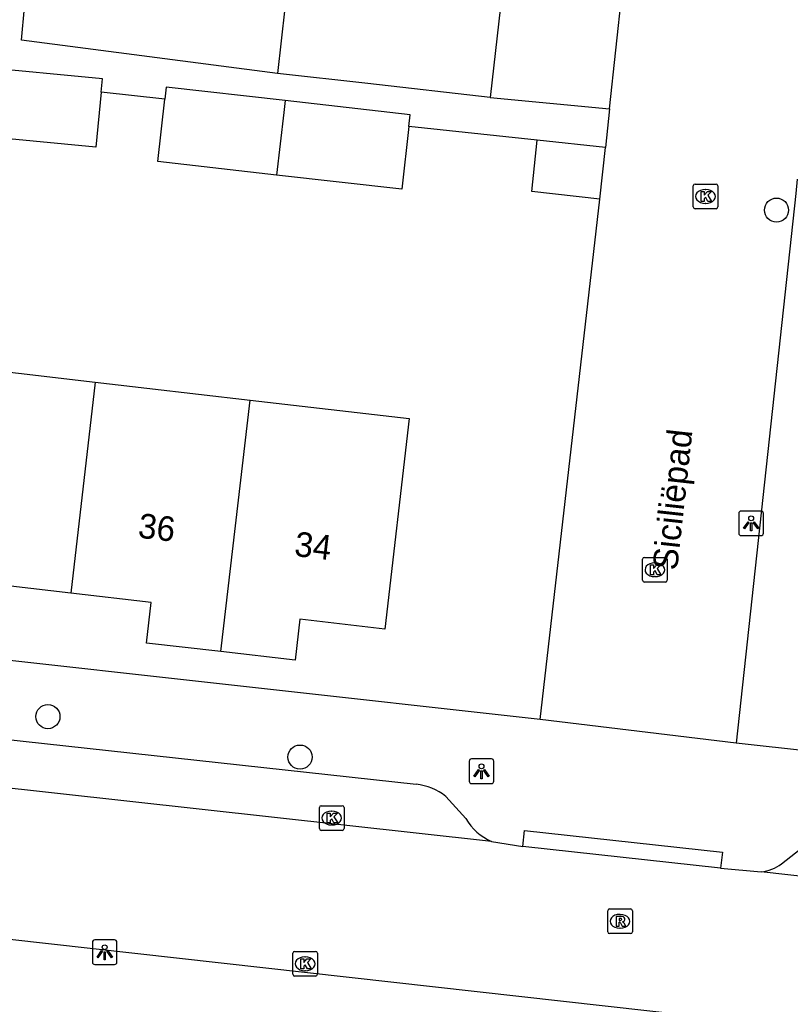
# Model space of a CAD drawing. Extents: x 162082 to 163393, y 388091 to 388632.
# Drawn here: x 162765.6 to 162796.87, y 388467.11 to 388507.04 of the extents above; entities that cross this region are included whole.
import ezdxf

# ---------------------------------------------------------------- set-up
doc = ezdxf.new("R2010")
doc.units = 0
for name, color, linetype in [('IMGEO_Boom', 7, 'Continuous'), ('IMGEO_Kolk', 7, 'Continuous'), ('IMGEO_Lichtpunt', 7, 'Continuous'), ('IMGEO_Openbare_ruimte_label', 7, 'Continuous'), ('IMGEO_Pand', 7, 'Continuous'), ('IMGEO_Pand_nummerreeks', 7, 'Continuous'), ('IMGEO_Rijbaan_lokaal_open', 7, 'Continuous'), ('IMGEO_Rioolput', 7, 'Continuous'), ('IMGEO_Voetpad_open', 7, 'Continuous')]:
    doc.layers.add(name, color=color, linetype=linetype)

msp = doc.modelspace()

# ---------------------------------------------------------------- linework, layer by layer
at = {"layer": 'IMGEO_Boom'}
for centre in [(162796.309, 388499.32), (162766.75, 388478.777), (162776.978, 388477.137)]:
    msp.add_circle(centre, 0.489, dxfattribs=at)
at = {"layer": 'IMGEO_Kolk'}
for p, q in [((162793.005, 388500.375), (162793.857, 388500.375)), ((162792.93, 388499.449), (162792.93, 388500.301)), ((162793.418, 388500.155), (162793.443, 388500.155)), ((162793.931, 388500.301), (162793.931, 388499.449)), ((162793.441, 388499.595), (162793.416, 388499.595)), ((162793.857, 388499.375), (162793.005, 388499.375)), ((162790.95, 388485.234), (162791.802, 388485.234)), ((162790.875, 388484.308), (162790.875, 388485.16)), ((162791.363, 388485.014), (162791.388, 388485.014)), ((162791.876, 388485.16), (162791.876, 388484.308)), ((162791.386, 388484.454), (162791.361, 388484.454)), ((162791.802, 388484.234), (162790.95, 388484.234)), ((162777.762, 388474.238), (162777.762, 388475.09)), ((162777.837, 388475.164), (162778.689, 388475.164)), ((162778.25, 388474.944), (162778.275, 388474.944)), ((162778.763, 388475.09), (162778.763, 388474.238)), ((162778.689, 388474.164), (162777.837, 388474.164)), ((162778.273, 388474.384), (162778.248, 388474.384)), ((162776.759, 388469.253), (162777.611, 388469.253)), ((162776.684, 388468.327), (162776.684, 388469.179)), ((162777.172, 388469.033), (162777.197, 388469.033)), ((162777.685, 388469.179), (162777.685, 388468.327)), ((162777.195, 388468.473), (162777.17, 388468.473)), ((162777.611, 388468.253), (162776.759, 388468.253))]:
    msp.add_line(p, q, dxfattribs=at)
for points in [[(162793.005, 388500.375), (162793.857, 388500.375)], [(162792.93, 388499.449), (162792.93, 388500.301)], [(162793.251, 388500.075), (162793.374, 388500.075), (162793.374, 388499.924), (162793.504, 388500.075), (162793.668, 388500.075), (162793.522, 388499.924), (162793.675, 388499.675), (162793.523, 388499.675), (162793.438, 388499.839), (162793.374, 388499.772), (162793.374, 388499.675), (162793.251, 388499.675), (162793.251, 388500.075)], [(162793.931, 388500.301), (162793.931, 388499.449)], [(162793.857, 388499.375), (162793.005, 388499.375)], [(162790.95, 388485.234), (162791.802, 388485.234)], [(162790.875, 388484.308), (162790.875, 388485.16)], [(162791.196, 388484.934), (162791.319, 388484.934), (162791.319, 388484.783), (162791.449, 388484.934), (162791.613, 388484.934), (162791.467, 388484.783), (162791.62, 388484.534), (162791.468, 388484.534), (162791.383, 388484.698), (162791.319, 388484.631), (162791.319, 388484.534), (162791.196, 388484.534), (162791.196, 388484.934)], [(162791.876, 388485.16), (162791.876, 388484.308)], [(162791.802, 388484.234), (162790.95, 388484.234)], [(162777.762, 388474.238), (162777.762, 388475.09)], [(162777.837, 388475.164), (162778.689, 388475.164)], [(162778.083, 388474.864), (162778.206, 388474.864), (162778.206, 388474.713), (162778.336, 388474.864), (162778.5, 388474.864), (162778.354, 388474.713), (162778.507, 388474.464), (162778.355, 388474.464), (162778.27, 388474.628), (162778.206, 388474.561), (162778.206, 388474.464), (162778.083, 388474.464), (162778.083, 388474.864)], [(162778.763, 388475.09), (162778.763, 388474.238)], [(162778.689, 388474.164), (162777.837, 388474.164)], [(162776.759, 388469.253), (162777.611, 388469.253)], [(162776.684, 388468.327), (162776.684, 388469.179)], [(162777.005, 388468.953), (162777.128, 388468.953), (162777.128, 388468.802), (162777.258, 388468.953), (162777.422, 388468.953), (162777.276, 388468.802), (162777.429, 388468.553), (162777.277, 388468.553), (162777.192, 388468.717), (162777.128, 388468.65), (162777.128, 388468.553), (162777.005, 388468.553), (162777.005, 388468.953)], [(162777.685, 388469.179), (162777.685, 388468.327)], [(162777.611, 388468.253), (162776.759, 388468.253)]]:
    msp.add_lwpolyline(points, dxfattribs=at)
for centre, start, end in [((162793.007, 388500.299), 91.552, 178.448), ((162793.007, 388500.299), 91.552, 178.448), ((162793.855, 388500.299), 1.552, 88.448), ((162793.855, 388500.299), 1.552, 88.448), ((162793.007, 388499.451), 181.552, 268.448), ((162793.007, 388499.451), 181.552, 268.448), ((162793.855, 388499.451), 271.552, 358.448), ((162793.855, 388499.451), 271.552, 358.448), ((162790.952, 388485.158), 91.552, 178.448), ((162790.952, 388485.158), 91.552, 178.448), ((162791.8, 388485.158), 1.552, 88.448), ((162791.8, 388485.158), 1.552, 88.448), ((162790.952, 388484.31), 181.552, 268.448), ((162790.952, 388484.31), 181.552, 268.448), ((162791.8, 388484.31), 271.552, 358.448), ((162791.8, 388484.31), 271.552, 358.448), ((162777.839, 388475.088), 91.552, 178.448), ((162777.839, 388475.088), 91.552, 178.448), ((162778.687, 388475.088), 1.552, 88.448), ((162778.687, 388475.088), 1.552, 88.448), ((162777.839, 388474.24), 181.552, 268.448), ((162777.839, 388474.24), 181.552, 268.448), ((162778.687, 388474.24), 271.552, 358.448), ((162778.687, 388474.24), 271.552, 358.448), ((162776.761, 388469.177), 91.552, 178.448), ((162776.761, 388469.177), 91.552, 178.448), ((162777.609, 388469.177), 1.552, 88.448), ((162777.609, 388469.177), 1.552, 88.448), ((162776.761, 388468.329), 181.552, 268.448), ((162776.761, 388468.329), 181.552, 268.448), ((162777.609, 388468.329), 271.552, 358.448), ((162777.609, 388468.329), 271.552, 358.448)]:
    msp.add_arc(centre, 0.0765, start, end, dxfattribs=at)
for centre, major_axis, ratio, start_param, end_param in [((162793.417, 388499.875), (-0.387, 0.002), 0.722429, 4.712389, 7.853982), ((162793.442, 388499.875), (-0.39, 0.002), 0.717154, 1.570796, 4.712389), ((162791.362, 388484.734), (-0.387, 0.002), 0.722429, 4.712389, 7.853982), ((162791.387, 388484.734), (-0.39, 0.002), 0.717154, 1.570796, 4.712389), ((162778.249, 388474.664), (-0.387, 0.002), 0.722429, 4.712389, 7.853982), ((162778.274, 388474.664), (-0.39, 0.002), 0.717154, 1.570796, 4.712389), ((162777.171, 388468.753), (-0.387, 0.002), 0.722429, 4.712389, 7.853982), ((162777.196, 388468.753), (-0.39, 0.002), 0.717154, 1.570796, 4.712389)]:
    msp.add_ellipse(centre, major_axis=major_axis, ratio=ratio, start_param=start_param, end_param=end_param, dxfattribs=at)
at = {"layer": 'IMGEO_Lichtpunt'}
for p, q in [((162794.781, 388487.02), (162794.781, 388486.213)), ((162794.781, 388487.02), (162794.781, 388486.213)), ((162795.683, 388487.115), (162794.875, 388487.115)), ((162795.683, 388487.115), (162794.875, 388487.115)), ((162795.777, 388486.213), (162795.777, 388487.02)), ((162795.777, 388486.213), (162795.777, 388487.02)), ((162794.875, 388486.119), (162795.683, 388486.119)), ((162794.875, 388486.119), (162795.683, 388486.119)), ((162783.842, 388476.965), (162783.842, 388476.158)), ((162783.842, 388476.965), (162783.842, 388476.158)), ((162784.744, 388477.06), (162783.936, 388477.06)), ((162784.744, 388477.06), (162783.936, 388477.06)), ((162784.838, 388476.158), (162784.838, 388476.965)), ((162784.838, 388476.158), (162784.838, 388476.965)), ((162783.936, 388476.064), (162784.744, 388476.064)), ((162783.936, 388476.064), (162784.744, 388476.064)), ((162768.555, 388469.625), (162768.555, 388468.818)), ((162768.555, 388469.625), (162768.555, 388468.818)), ((162769.457, 388469.72), (162768.649, 388469.72)), ((162769.457, 388469.72), (162768.649, 388469.72)), ((162769.551, 388468.818), (162769.551, 388469.625)), ((162769.551, 388468.818), (162769.551, 388469.625)), ((162768.649, 388468.724), (162769.457, 388468.724)), ((162768.649, 388468.724), (162769.457, 388468.724))]:
    msp.add_line(p, q, dxfattribs=at)
for points in [[(162795.155, 388486.684), (162795.194, 388486.656), (162795.006, 388486.394), (162794.968, 388486.421), (162795.155, 388486.684)], [(162795.257, 388486.636), (162795.304, 388486.636), (162795.304, 388486.314), (162795.257, 388486.314), (162795.257, 388486.636)], [(162795.367, 388486.656), (162795.405, 388486.683), (162795.592, 388486.421), (162795.553, 388486.393), (162795.367, 388486.656)], [(162784.216, 388476.629), (162784.255, 388476.601), (162784.067, 388476.339), (162784.029, 388476.366), (162784.216, 388476.629)], [(162784.318, 388476.581), (162784.365, 388476.581), (162784.365, 388476.259), (162784.318, 388476.259), (162784.318, 388476.581)], [(162784.428, 388476.601), (162784.466, 388476.628), (162784.653, 388476.366), (162784.614, 388476.338), (162784.428, 388476.601)], [(162768.929, 388469.289), (162768.968, 388469.261), (162768.78, 388468.999), (162768.742, 388469.026), (162768.929, 388469.289)], [(162769.031, 388469.241), (162769.078, 388469.241), (162769.078, 388468.919), (162769.031, 388468.919), (162769.031, 388469.241)], [(162769.141, 388469.261), (162769.179, 388469.288), (162769.366, 388469.026), (162769.327, 388468.998), (162769.141, 388469.261)]]:
    msp.add_lwpolyline(points, dxfattribs=at)
for centre in [(162795.28, 388486.818), (162784.341, 388476.763), (162769.054, 388469.423)]:
    msp.add_circle(centre, 0.0994, dxfattribs=at)
for centre, start, end in [((162794.875, 388487.02), 90, 180), ((162794.875, 388487.02), 90, 180), ((162795.683, 388487.02), 0, 90), ((162795.683, 388487.02), 0, 90), ((162794.875, 388486.213), 180, 270), ((162794.875, 388486.213), 180, 270), ((162795.683, 388486.213), 270, 0), ((162795.683, 388486.213), 270, 360), ((162783.936, 388476.965), 90, 180), ((162783.936, 388476.965), 90, 180), ((162784.744, 388476.965), 0, 90), ((162784.744, 388476.965), 0, 90), ((162783.936, 388476.158), 180, 270), ((162783.936, 388476.158), 180, 270), ((162784.744, 388476.158), 270, 0), ((162784.744, 388476.158), 270, 360), ((162768.649, 388469.625), 90, 180), ((162768.649, 388469.625), 90, 180), ((162769.457, 388469.625), 0, 90), ((162769.457, 388469.625), 0, 90), ((162768.649, 388468.818), 180, 270), ((162768.649, 388468.818), 180, 270), ((162769.457, 388468.818), 270, 0), ((162769.457, 388468.818), 270, 360)]:
    msp.add_arc(centre, 0.0946, start, end, dxfattribs=at)
at = {"layer": 'IMGEO_Pand'}
for points in [[(162776.811, 388511.504), (162776.059, 388504.867)], [(162787.051, 388510.34), (162786.717, 388507.393), (162785.114, 388507.574), (162784.697, 388503.888)], [(162768.909, 388504.11), (162768.961, 388504.651), (162763.858, 388505.137)], [(162784.697, 388503.888), (162779.729, 388504.451), (162776.059, 388504.867)], [(162768.909, 388504.11), (162768.696, 388501.874), (162763.594, 388502.359)], [(162776.379, 388503.76), (162771.549, 388504.308), (162771.494, 388503.827)], [(162776.026, 388500.742), (162771.206, 388501.288), (162771.494, 388503.827)], [(162776.379, 388503.76), (162776.323, 388503.28), (162776.026, 388500.742)], [(162781.395, 388502.707), (162781.449, 388503.185), (162776.379, 388503.76)], [(162781.395, 388502.707), (162781.106, 388500.167), (162776.026, 388500.742)], [(162789.139, 388499.763), (162786.382, 388500.073), (162786.604, 388502.153)], [(162789.374, 388501.858), (162786.604, 388502.153)], [(162789.139, 388499.763), (162789.374, 388501.858)], [(162762.437, 388493.072), (162768.673, 388492.346)], [(162768.673, 388492.346), (162767.681, 388483.788)], [(162768.673, 388492.346), (162774.959, 388491.615)], [(162773.766, 388481.412), (162774.959, 388491.615)], [(162774.959, 388491.615), (162781.408, 388490.864), (162780.415, 388482.328), (162776.973, 388482.728), (162776.779, 388481.061), (162773.766, 388481.412)], [(162767.681, 388483.788), (162764.425, 388484.167), (162764.226, 388482.461), (162761.236, 388482.809)], [(162773.766, 388481.412), (162770.748, 388481.763), (162770.939, 388483.409), (162767.681, 388483.788)]]:
    msp.add_lwpolyline(points, dxfattribs=at)
at = {"layer": 'IMGEO_Rijbaan_lokaal_open'}
for points in [[(162789.54, 388503.424), (162790.046, 388508.201)], [(162789.54, 388503.424), (162789.374, 388501.858)], [(162797.153, 388500.577), (162797.091, 388500), (162794.676, 388477.705)], [(162786.727, 388478.655), (162789.139, 388499.763)], [(162784.746, 388473.713), (162740.592, 388478.592)], [(162794.676, 388477.705), (162786.727, 388478.655)], [(162784.746, 388473.713), (162786.019, 388473.51)], [(162794.041, 388472.628), (162786.019, 388473.51)], [(162794.041, 388472.628), (162795.687, 388472.482)], [(162846.818, 388466.733), (162795.687, 388472.482)], [(162757.624, 388470.527), (162759.881, 388470.341), (162827.517, 388462.78)]]:
    msp.add_lwpolyline(points, dxfattribs=at)
at = {"layer": 'IMGEO_Rioolput'}
for p, q in [((162789.461, 388470.049), (162789.461, 388470.901)), ((162789.536, 388470.975), (162790.388, 388470.975)), ((162790.462, 388470.901), (162790.462, 388470.049)), ((162789.949, 388470.755), (162789.974, 388470.755)), ((162789.972, 388470.195), (162789.947, 388470.195)), ((162790.388, 388469.975), (162789.536, 388469.975))]:
    msp.add_line(p, q, dxfattribs=at)
for points in [[(162789.461, 388470.049), (162789.461, 388470.901)], [(162789.536, 388470.975), (162790.388, 388470.975)], [(162790.462, 388470.901), (162790.462, 388470.049)], [(162790.05, 388470.673), (162789.798, 388470.675), (162789.798, 388470.275)], [(162789.798, 388470.275), (162789.922, 388470.275), (162789.922, 388470.437), (162789.933, 388470.437)], [(162789.976, 388470.594), (162789.922, 388470.594), (162789.922, 388470.513)], [(162789.922, 388470.513), (162789.974, 388470.513)], [(162789.98, 388470.408), (162790.051, 388470.275), (162790.191, 388470.275), (162790.126, 388470.401)], [(162790.388, 388469.975), (162789.536, 388469.975)]]:
    msp.add_lwpolyline(points, dxfattribs=at)
for centre, radius, start, end in [((162789.538, 388470.899), 0.0765, 91.552, 178.448), ((162789.538, 388470.899), 0.0765, 91.552, 178.448), ((162790.386, 388470.899), 0.0765, 1.552, 88.448), ((162790.386, 388470.899), 0.0765, 1.552, 88.448), ((162789.932, 388470.384), 0.0533, 26.0293, 88.6989), ((162789.958, 388470.702), 0.19, 274.7715, 282.9687), ((162789.982, 388470.498), 0.0964, 77.0061, 93.1865), ((162789.996, 388470.555), 0.0378, 276.6634, 79.6772), ((162790.049, 388470.563), 0.109, 350.3612, 89.416), ((162790.047, 388470.563), 0.112, 277.5842, 350.9817), ((162790.031, 388470.348), 0.108, 29.5134, 73.7905), ((162789.538, 388470.051), 0.0765, 181.552, 268.448), ((162789.538, 388470.051), 0.0765, 181.552, 268.448), ((162790.386, 388470.051), 0.0765, 271.552, 358.448), ((162790.386, 388470.051), 0.0765, 271.552, 358.448)]:
    msp.add_arc(centre, radius, start, end, dxfattribs=at)
for centre, major_axis, ratio, start_param, end_param in [((162789.948, 388470.475), (-0.387, 0.002), 0.722429, 4.712389, 7.853982), ((162789.973, 388470.475), (-0.39, 0.002), 0.717154, 1.570796, 4.712389)]:
    msp.add_ellipse(centre, major_axis=major_axis, ratio=ratio, start_param=start_param, end_param=end_param, dxfattribs=at)
at = {"layer": 'IMGEO_Voetpad_open'}
for points in [[(162776.059, 388504.867), (162765.675, 388506.212), (162765.798, 388507.537)], [(162771.494, 388503.827), (162768.909, 388504.11)], [(162784.697, 388503.888), (162789.54, 388503.424)], [(162786.604, 388502.153), (162781.395, 388502.707)], [(162786.727, 388478.655), (162739.055, 388483.959)], [(162743.484, 388480.216), (162781.685, 388476.037)], [(162847.118, 388471.904), (162794.676, 388477.705)], [(162782.9, 388475.544), (162783.71, 388474.643)], [(162786.019, 388473.51), (162786.091, 388474.165), (162794.113, 388473.277), (162794.041, 388472.628)], [(162796.513, 388472.804), (162797.654, 388473.697)]]:
    msp.add_lwpolyline(points, dxfattribs=at)
for centre, radius, start, end in [((162781.402, 388473.595), 2.458, 52.4458, 83.3834), ((162785.67, 388475.785), 2.269, 210.2168, 245.9556), ((162795.477, 388474.24), 1.77, 276.798, 305.7967)]:
    msp.add_arc(centre, radius, start, end, dxfattribs=at)

# ---------------------------------------------------------------- texts
at = {"layer": 'IMGEO_Openbare_ruimte_label'}
msp.add_text('Siciliëpad', height=1, rotation=83.6851, dxfattribs=at).set_placement((162792.274, 388484.684))
at = {"layer": 'IMGEO_Pand_nummerreeks'}
for s, p in [('36', (162770.374, 388486.04)), ('34', (162776.716, 388485.297))]:
    msp.add_text(s, height=1, rotation=353.3254, dxfattribs=at).set_placement(p)

doc.saveas('drawing.dxf')
